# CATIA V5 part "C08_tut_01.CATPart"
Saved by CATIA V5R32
Part number: Part1
Bounding box of the stored display mesh (mm): x -175 to 175, y -250 to 250, z -8 to 100
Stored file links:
  D:\PROJECTS\Project 2022\CATIA V5 6R 2022\Resources\Tutorial Files\c08_catia_v5_6r2022_tut\C08_tut_01.CATPart
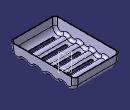
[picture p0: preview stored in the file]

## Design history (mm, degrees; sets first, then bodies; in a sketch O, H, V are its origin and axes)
Body1 (main body)
  Sketch1 on yz-plane, origin (0, 0, 0), H (0, 1, 0), V (0, 0, 1)
    point P1 (-250, 0)
    line L1 (-250, 0) -> (250, 0)
    line L2 (250, 0) -> (250, 100)
    line L3 (250, 100) -> (-250, 100)
    line L4 (-250, 100) -> (-250, 0)
    length L3 = 500
    length L2 = 100
    distance V L2 = 250
    coincidence: P1 H
    horizontal: L1 H, L3 H
    vertical: L2 V, L4 V
  Pad1: profile Sketch1, direction (1, 0, 0), length 175, mirrored extent
  Draft1: Angle -5, Neutral face of Pad1 from Sketch1.L3, PullDir face of Pad1 from Sketch1.L3
  Sketch2 on yz-plane, origin (0, 0, 0), H (0, 1, 0), V (0, 0, 1)
    arc A1 centre (-195.4346, 50) radius 50 from (-245.2443, 45.6422) to (-162.8621, 12.0654) ccw
    reference projected line E1 (-241.2511, 0) -> (-250, 100) from edge [end face of Pad1 | face of Pad1 from Sketch1.L4]
    reference projected line E2 (241.2511, 0) -> (-241.2511, 0) from edge [end face of Pad1 | face of Pad1 from Sketch1.L1]
    arc A2 centre (195.4346, 50) radius 50 from (162.8622, 12.0653) to (245.2443, 45.6422) ccw
    reference projected line E3 (250, 100) -> (241.2511, 0) from edge [end face of Pad1 | face of Pad1 from Sketch1.L2]
    reference projected line E4 (241.2511, 0) -> (-241.2511, 0) from edge [end face of Pad1 | face of Pad1 from Sketch1.L1]
    point P3 (97.7173, 50)
    point P4 (0, 50)
    point P5 (-97.7173, 50)
    construction line L1 (195.4346, 50) -> (-195.4346, 50)
    point P7 (-48.8586, -6.902)
    projected line E5 (250, 100) -> (241.2511, 0) from edge [end face of Pad1 | face of Pad1 from Sketch1.L2]
    projected line E6 (-241.2511, 0) -> (-250, 100) from edge [end face of Pad1 | face of Pad1 from Sketch1.L4]
    arc A3 centre (97.7173, 50) radius 50 from (65.1449, 12.0653) to (130.2898, 12.0654) ccw
    arc A4 centre (0, 50) radius 50 from (-32.5724, 12.0653) to (32.5725, 12.0654) ccw
    arc A5 centre (-97.7173, 50) radius 50 from (-130.2897, 12.0653) to (-65.1448, 12.0654) ccw
    point P23 (-245.2443, 45.6422)
    arc A6 centre (-146.5759, -6.902) radius 25 from (-130.2897, 12.0653) to (-162.8621, 12.0654) ccw
    arc A7 centre (-48.8586, -6.902) radius 25 from (-32.5724, 12.0653) to (-65.1448, 12.0654) ccw
    arc A8 centre (48.8586, -6.902) radius 25 from (65.1449, 12.0653) to (32.5725, 12.0654) ccw
    arc A9 centre (146.5759, -6.902) radius 25 from (162.8622, 12.0653) to (130.2898, 12.0654) ccw
    axis line L2 (146.5759, -6.902) -> (-146.5759, -6.902)
    line L3 (245.2443, 45.6422) -> (237.7725, -39.761)
    line L4 (-245.2443, 45.6422) -> (-237.7725, -39.761)
    line L5 (-237.7725, -39.761) -> (237.7725, -39.761)
    radius A1 = 50
    radius A6 = 25
    radius A5 = 50
    radius A7 = 25
    radius A4 = 50
    radius A8 = 25
    radius A3 = 50
    radius A9 = 25
    tangency: A1 E1, A1 E2, A2 E3, A2 E4, A6 A5, A7 A5, A6 A1, A7 A4, A8 A4, A8 A3, A3 A9, A9 A2, L3 A2, L4 A1
    horizontal: L1 H, L2 H, L5 H
    coincidence: P3 L1, P4 L1, P5 L1, P4 V, E6 P23, L2 P7
  Pocket1: profile Sketch2, direction (-1, 0, 0), through (limit type 3), opposite side length 175
  Fillet1: radius 25, on edge [face of Pocket1 | end face of Pad1]; edge [start face of Pad1 | face of Pad1 from Sketch1.L2]
  Shell1: ExtOffset 0, Face face of Pad1 from Sketch1.L3, IntOffset 5
  Sketch3 on xy-plane, origin (0, 0, 0), H (1, 0, 0), V (0, 1, 0)
    point P1 (0, 195.4)
    line L1 (105, 183.4) -> (-105, 183.4)
    line L2 (-105, 207.4) -> (105, 207.4)
    arc A1 centre (105, 195.4) radius 12 from (105, 183.4) to (105, 207.4) ccw
    point P6 (105, 195.4)
    arc A2 centre (-105, 195.4) radius 12 from (-105, 207.4) to (-105, 183.4) ccw
    point P7 (-105, 195.4)
    point P8 (-105, 207.4)
    axis line L3 (105, 195.4) -> (-105, 195.4)
    reference projected line E1 (175, 250) -> (-175, 250) from edge [face of Pad1 from Sketch1.L2 | face of Pad1 from Sketch1.L3]
    distance P6 P7 = 210
    distance V P7 = 105
    distance L2 L1 = 24
    distance E1 L3 = 54.6
    coincidence: P1 V, A2 P8
    horizontal: L1 H, L2 H, L3 H
    equidistance: L1 L2 P1
    tangency: A1 L1, A2 L2, A1 L2, L1 A2
  Pocket2: profile Sketch3, direction (0, 0, -1), through (limit type 6), opposite side length 25
  RectPattern1: of Pocket2, direction 1 instances 5, spacing 97.7, along edge [end face of Pad1 | face of Pad1 from Sketch1.L3] reversed
  Sketch4 on xy-plane, origin (0, 0, 0), H (1, 0, 0), V (0, 1, 0)
    circle A1 centre (-135, -196) radius 10
    point P1 (-135, -196)
    reference projected line E1 (-175, 250) -> (-175, -250) from edge [start face of Pad1 | face of Pad1 from Sketch1.L3]
    reference projected line E2 (-175, -250) -> (175, -250) from edge [face of Pad1 from Sketch1.L4 | face of Pad1 from Sketch1.L3]
    radius A1 = 10
    distance E1 P1 = 40
    distance P1 E2 = 54
  Pad2: profile Sketch4, direction (0, 0, 1), up to the existing solid (limit type 2), opposite side length 8
  RectPattern2: of Pad2, direction 1 instances 2, spacing 390.8, along edge [start face of Pad1 | face of Pad1 from Sketch1.L3] reversed, direction 2 instances 2, spacing 270, along edge [face of Pad1 from Sketch1.L4 | face of Pad1 from Sketch1.L3]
